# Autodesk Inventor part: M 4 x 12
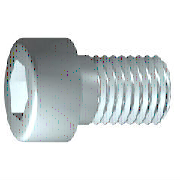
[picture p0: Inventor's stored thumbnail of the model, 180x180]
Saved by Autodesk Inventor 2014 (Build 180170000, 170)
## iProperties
IsCustomPart: 0
Created: 2009-02
Part Number: M 4 x 12
Material: 강, 연강
Description: 6각머리 태핑 나사
Document SubType Name: Modeling
Standard: KS B 1003
Designer: KYOUNG IL JANG
Standards Organization: KS
Language: ko-KR
Size Designation: M 4 x 12
Categories: <MemberInstance><Categories><Category DisplayName="조임쇠" InternalName="e4da775c-781d-43d5-af7c-5136215cf5a6" Mnemonic="FSTN"><Category DisplayName="볼트" InternalN
Density: 7.86 g/cm^3
Mass: 2.23465 g
Surface Area: 3.30853 cm^2
Volume: 0.284306 cm^3
Appearance: 강철
Author: KYOUNG IL JANG
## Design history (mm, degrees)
sketch "스케치1"
  geometry: L1 (-1, 0)-(12, 0); L2 (12, 0)-(12, 2); L3 (12, 2)-(1.75, 2); L4 (1.75, 2)-(1.32, 2); L5 (1.32, 2)-(0, 2); L6 (0, 2)-(0, 3.5); L7 (0, 3.5)-(-4, 3.5); L8 (-4, 3.5)-(-4, 1.732); L9 (-4, 1.732)-(-2, 1.732); L10 (-2, 1.732)-(-1, 0); L11 (-7.2, 0)-(15.2, 0) reference; L12 (0, -0.7)-(0, 4.2) reference; L13 (1.75, 2)-(0, 2)
  constraints: 22 end point, 6 parallel, 2 collinear, 2 perpendicular, 1 horizontal, 1 point on line
  dimensions: "d1" = 10.25 distance from line of L3.end L2 (= GEL); "d2" = 0.42952 distance of L4.end L3.end (computed from GAL); "d3" = 4 distance between parallel lines of L8 L6 (= KOH); "d4" = 2 distance of L8.end L9.end (= INTI); "d5" = 60 deg angle of L10 L1; "d6" = 4 diameter of L3 L1 (= GD); "d7" = 4 diameter of L5 L1 (= BDM); "d8" = 3.4641 diameter of L9 L1 (= 1.1547 x SW); "d9" = 7 diameter of L7 L1 (= KOD); "d26" = 12 distance between parallel lines of L12 L2 (= NLG)
revolve "본체" sketch "스케치1" stored, may be unused: angle "d10" = 90 deg
sketch "스케치2"
  geometry: L1 (0, -4.9)-(0, 4.9) reference; L2 (-4.9, 0)-(4.9, 0) reference; L3 (1.732, 0)-(0.866, -1.5); L4 (0.866, -1.5)-(-0.866, -1.5); L5 (-0.866, -1.5)-(-1.732, 0); L6 (-1.732, 0)-(-0.866, 1.5); L7 (-0.866, 1.5)-(0.866, 1.5); L8 (0.866, 1.5)-(1.732, 0); 2 further points
  constraints: 12 end point, 1 coincident, 1 horizontal alignment, 1 point on line, 12 other
extrude "슬롯" join sketch "스케치2" stored distance "d11" = 10; taper "d12" = 0 deg
workplane "Work Plane1"
fillet "Fillet2" dims "d30" = 0.1 (= R)
body "Solid1"
fillet "모깎기1" dims "d17" = 0.4 (= RR)
feature "스레드" dims "d13" = 10.25 (= GEL), "d14" = 0
chamfer "모따기1" distance "d15" = 0.42941 (= -0.5 x SPD + 0.5 x GD); stored, may be unused: second distance "d16" = 0.42941 (= GUL), angle "d27" = 45 deg
other parameters: "GD" = 4 (= NND) [user parameter; used in 2 equation terms], "NLG" = 12 [user parameter; used in 1 equation term], "GEL" = 10.25 [user parameter; used in 2 equation terms], "KOD" = 7 [user parameter; used in 1 equation term], "KOH" = 4 [user parameter; used in 1 equation term], "INTI" = 2 [user parameter; used in 1 equation term], "GAL" = 0.42941 (= 0.61345 x PTC) [user parameter; used in 1 equation term], "GUL" = 0.42941 (= 0.61345 x PTC) [user parameter; used in 1 equation term], "BDM" = 4 (= NND) [user parameter; used in 1 equation term], "SW" = 3 [user parameter; used in 2 equation terms], "RR" = 0.4 [user parameter; used in 1 equation term], "SPD" = 3.14117 (= NND - 1.2269 x PTC) [user parameter; used in 1 equation term], "d19" = 0, "d28" = 0, "d29" = 0, "R" = 0.1 [user parameter; used in 1 equation term], "PHH" = 0.2 [user parameter], "GD1" = 3.14117 (= THREADDIA - 1.2269 x PTC) [user parameter], "THREADDIA" = 4 [user parameter; used in 1 equation term], "FAWI" = 45 deg [user parameter], "TPU" = 14.28571 (computed from PTC) [user parameter], "PTC" = 0.7 [user parameter; used in 5 equation terms], "NND" = 4 [user parameter; used in 3 equation terms], "TOA" = 30 deg [user parameter], "E0" = 3.465 (= 1.155 x SW) [user parameter]
